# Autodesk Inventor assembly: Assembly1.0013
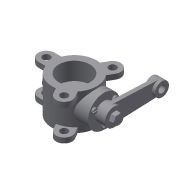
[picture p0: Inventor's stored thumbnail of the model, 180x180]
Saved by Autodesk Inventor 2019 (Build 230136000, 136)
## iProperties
Created: 2016-07
Part Number: Assembly1.0013
Document SubType Name: Assembly
Designer: Sandeep
Author: Sandeep
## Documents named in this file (10)
- E:\_Deepak\Inventor\Projects\Autodesk Inventor_2019_Project\Resources\Inventor_2018_tut\c09_Inv_2019_tut\c09_Inv_tut_2019\c09_tut01_inv\OldVersions\Assembly1.0013.iam
- E:\_Deepak\Inventor\Projects\Autodesk Inventor_2019_Project\Resources\Inventor_2018_tut\c09_Inv_2019_tut\c09_Inv_tut_2019\c09_tut01_inv\Butterfly Valve\Body.ipt
- E:\_Deepak\Inventor\Projects\Autodesk Inventor_2019_Project\Resources\Inventor_2018_tut\c09_Inv_2019_tut\c09_Inv_tut_2019\c09_tut01_inv\Butterfly Valve\shaft1.ipt
- E:\_Deepak\Inventor\Projects\Autodesk Inventor_2019_Project\Resources\Inventor_2018_tut\c09_Inv_2019_tut\c09_Inv_tut_2019\c09_tut01_inv\Butterfly Valve\Arm1.ipt
- E:\_Deepak\Inventor\Projects\Autodesk Inventor_2019_Project\Resources\Inventor_2018_tut\c09_Inv_2019_tut\c09_Inv_tut_2019\c09_tut01_inv\Butterfly Valve\Retainer.ipt
- E:\_Deepak\Inventor\Projects\Autodesk Inventor_2019_Project\Resources\Inventor_2018_tut\c09_Inv_2019_tut\c09_Inv_tut_2019\c09_tut01_inv\Butterfly Valve\scew1.ipt
- E:\_Deepak\Inventor\Projects\Autodesk Inventor_2019_Project\Resources\Inventor_2018_tut\c09_Inv_2019_tut\c09_Inv_tut_2019\c09_tut01_inv\Butterfly Valve\Plate.ipt
- E:\_Deepak\Inventor\Projects\Autodesk Inventor_2019_Project\Resources\Inventor_2018_tut\c09_Inv_2019_tut\c09_Inv_tut_2019\c09_tut01_inv\Butterfly Valve\Screw.ipt
- E:\_Deepak\Inventor\Projects\Autodesk Inventor_2019_Project\Resources\Inventor_2018_tut\c09_Inv_2019_tut\c09_Inv_tut_2019\c09_tut01_inv\Butterfly Valve\Nut.ipt
- E:\_Deepak\Inventor\Projects\Autodesk Inventor_2019_Project\Resources\Inventor_2018_tut\c09_Inv_2019_tut\c09_Inv_tut_2019\c09_tut01_inv\Butterfly Valve\Parallel key.ipt
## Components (12 placed, 9 different names)
1. Body:2 — Mate:1, Insert:2, Insert:3, Angle:3, Insert:12
2. shaft1:1 — Angle:2, Angle:3, Insert:5, Insert:6, Insert:12, Insert:13, Mate:4
3. Retainer:1 — Mate:1, Insert:2, Insert:3, Insert:4, Angle:1, Insert:9, Insert:10, Insert:11, Mate:2
4. Arm1:2 — Insert:4, Angle:1, Angle:2, Mate:3
5. scew1:1 — Insert:7
6. scew1:2 — Insert:8
7. Plate:1 — Insert:5, Insert:6, Insert:7, Insert:8
8. Screw:1 — Insert:9
9. Screw:2 — Insert:10
10. Screw:3 — Insert:11
11. Nut:1 — Insert:13
12. Parallel key:1 — Mate:2, Mate:3, Mate:4
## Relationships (19: Insert 12, Mate 4, Angle 3)
- Mate:1: Body:2 ↔ Retainer:1
- Insert:2: Body:2 ↔ Retainer:1
- Insert:3: Body:2 ↔ Retainer:1
- Insert:4: Retainer:1 ↔ Arm1:2
- Angle:1: Retainer:1 ↔ Arm1:2
- Angle:2: shaft1:1 ↔ Arm1:2
- Angle:3: Body:2 ↔ shaft1:1
- Insert:5: shaft1:1 ↔ Plate:1
- Insert:6: shaft1:1 ↔ Plate:1
- Insert:7: scew1:1 ↔ Plate:1
- Insert:8: scew1:2 ↔ Plate:1
- Insert:9: Retainer:1 ↔ Screw:1
- Insert:10: Retainer:1 ↔ Screw:2
- Insert:11: Retainer:1 ↔ Screw:3
- Insert:12: Body:2 ↔ shaft1:1
- Insert:13: shaft1:1 ↔ Nut:1
- Mate:2: Retainer:1 ↔ Parallel key:1
- Mate:3: Arm1:2 ↔ Parallel key:1
- Mate:4: shaft1:1 ↔ Parallel key:1
